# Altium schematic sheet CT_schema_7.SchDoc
size 251 x 159 mm
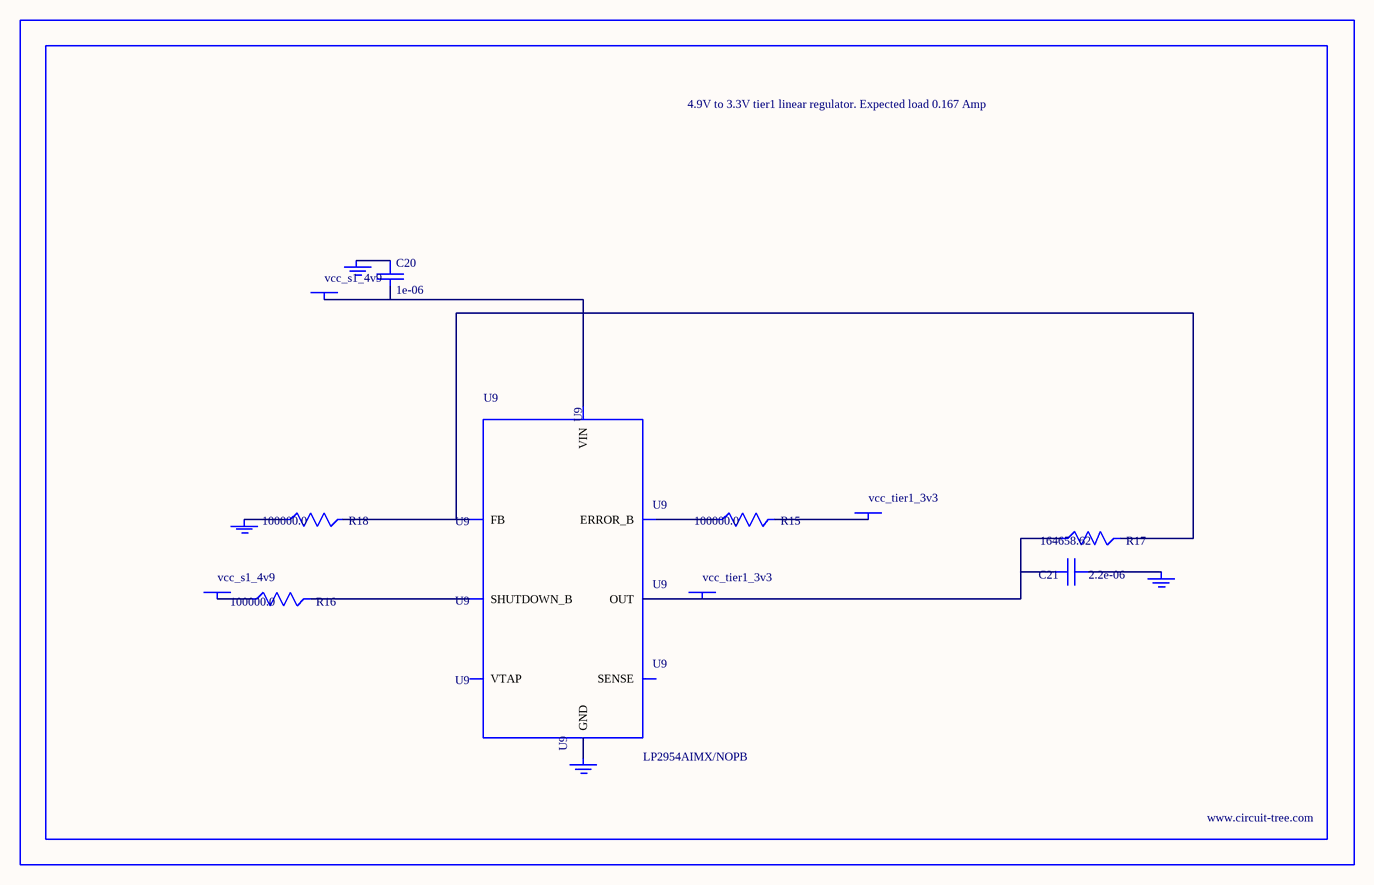
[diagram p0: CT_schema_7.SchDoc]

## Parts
BORDER6  (no value)
C20  1e-06  [EXV-9B]
C21  2.2e-06  [EXV-9B]
GND_INSTANCE_6_0  (no value)
GND_INSTANCE_6_1  (no value)
GND_INSTANCE_6_2  (no value)
GND_INSTANCE_6_3  (no value)
POWER_INSTANCE_6_0  vcc_s1_4v9
POWER_INSTANCE_6_1  vcc_tier1_3v3
POWER_INSTANCE_6_2  vcc_s1_4v9
POWER_INSTANCE_6_3  vcc_tier1_3v3
R15  100000.0  [R0603]
R16  100000.0  [R0603]
R17  164658.62  [R0603]
R18  100000.0  [R0603]
U9  LP2954AIMX/NOPB  [LP2954]

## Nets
NetC20_1: C20.1 GND_INSTANCE_6_2.0(GND)
NetC20_2: C20.2 POWER_INSTANCE_6_2.0(PWR) U9.8(VIN)
NetC21_1: C21.1 GND_INSTANCE_6_0.0(GND)
NetC21_2: C21.2 POWER_INSTANCE_6_3.0(PWR) R17.1 U9.1(OUT)
NetGND_INSTANCE_6_1_0: GND_INSTANCE_6_1.0(GND) R18.1
NetGND_INSTANCE_6_3_0: GND_INSTANCE_6_3.0(GND) U9.4(GND)
NetPOWER_INSTANCE_6_0_0: POWER_INSTANCE_6_0.0(PWR) R16.1
NetPOWER_INSTANCE_6_1_0: POWER_INSTANCE_6_1.0(PWR) R15.2
NetR15_1: R15.1 U9.5(ERROR_B)
NetR16_2: R16.2 U9.3(SHUTDOWN_B)
NetR17_2: R17.2 R18.2 U9.7(FB)

Not connected (* = marked no-connect by the designer): U9 2(SENSE) 6(VTAP)

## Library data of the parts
BORDER6 = BORDER_PAGE6
C20 = EDK105M050A9BAA
C21 = EDK225M050A9BAA
GND_INSTANCE_6_0-GND_INSTANCE_6_3 = GND
POWER_INSTANCE_6_0-POWER_INSTANCE_6_3 = PWR
R15 R16 R18 = RC0603JR-07100KL
R17 = R17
